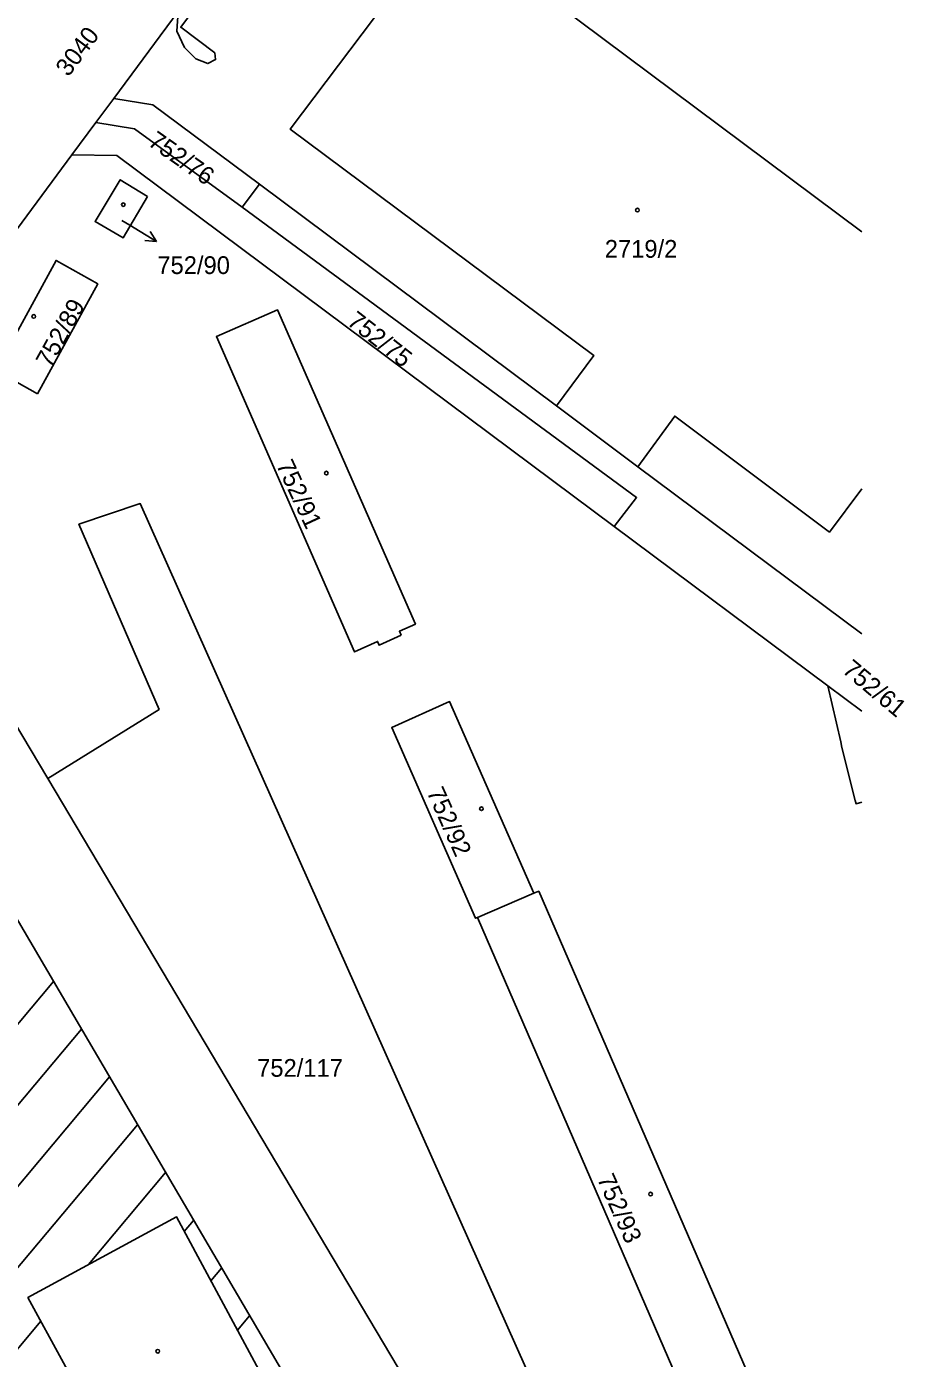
# Model space of a CAD drawing. Extents: x -496682 to -495776, y -1088797 to -1088018.
# Drawn here: x -496080.3 to -495996.2, y -1088434.2 to -1088306.6 of the extents above; entities that cross this region are included whole.
import ezdxf

# ---------------------------------------------------------------- set-up
doc = ezdxf.new("R2010")
doc.units = 0
for name, color, linetype in [('Hranice parcel', 7, 'Continuous'), ('Parcelní čísla', 7, 'Continuous'), ('Pop  PČ popisy', 7, 'Continuous'), ('Vrstva 20', 7, 'Continuous'), ('Značky budov', 7, 'Continuous')]:
    doc.layers.add(name, color=color, linetype=linetype)

msp = doc.modelspace()

# ---------------------------------------------------------------- linework, layer by layer
at = {"layer": 'Hranice parcel'}
for p, q in [((-496071.94, -1088313.44), (-496065.77, -1088305.12)), ((-496073.66, -1088315.77), (-496071.94, -1088313.44)), ((-496075.94, -1088318.85), (-496073.66, -1088315.77)), ((-496096.94, -1088347.2), (-496075.94, -1088318.85)), ((-496057.99, -1088321.67), (-496059.64, -1088323.87)), ((-496029.52, -1088342.93), (-496057.99, -1088321.67)), ((-496021.73, -1088348.76), (-496029.52, -1088342.93)), ((-496078.26, -1088378.65), (-496096.94, -1088347.2)), ((-496000.29, -1088364.76), (-496021.73, -1088348.76)), ((-496024.01, -1088354.47), (-496003.54, -1088369.74)), ((-496003.54, -1088369.74), (-496000.29, -1088372.17)), ((-496037.08, -1088391.95), (-496031.69, -1088389.64))]:
    msp.add_line(p, q, dxfattribs=at)
for points in [[(-496065.77, -1088305.12), (-496065.88, -1088306.99), (-496065.17, -1088308.57), (-496064.07, -1088309.66), (-496062.92, -1088310.11), (-496062.18, -1088309.72), (-496062.26, -1088309.09), (-496065.52, -1088306.62), (-496050.59, -1088286.56), (-496047.31, -1088288.98), (-496046.7, -1088288.89), (-496046.63, -1088288.12), (-496048.32, -1088286.61), (-496049.69, -1088286.17), (-496051.08, -1088286.43), (-496052.45, -1088287.51)], [(-496000.29, -1088326.22), (-496036.42, -1088299.21), (-496034.84, -1088297.11), (-496038.16, -1088294.64), (-496039.76, -1088296.76), (-496040.07, -1088296.53), (-496055.03, -1088316.4), (-496025.94, -1088338.1), (-496029.52, -1088342.93)], [(-496057.99, -1088321.67), (-496068.19, -1088314.06), (-496071.94, -1088313.44)], [(-496059.64, -1088323.87), (-496069.94, -1088316.36), (-496073.66, -1088315.77)], [(-496075.94, -1088318.85), (-496071.64, -1088318.92), (-496024.01, -1088354.47)], [(-496068.69, -1088322.84), (-496071.32, -1088321.24), (-496073.72, -1088325.26), (-496071.02, -1088326.81), (-496068.69, -1088322.84)], [(-496059.64, -1088323.87), (-496021.85, -1088351.71), (-496024.01, -1088354.47)], [(-496079.25, -1088341.76), (-496073.47, -1088331.22), (-496077.46, -1088328.98), (-496083.24, -1088339.52), (-496079.25, -1088341.76)], [(-496044.4, -1088364.9), (-496044.57, -1088364.53), (-496043.04, -1088363.83), (-496056.25, -1088333.7), (-496062.1, -1088336.28), (-496048.87, -1088366.5), (-496046.66, -1088365.5), (-496046.52, -1088365.86), (-496044.4, -1088364.9)], [(-496021.73, -1088348.76), (-496018.2, -1088343.9), (-496003.38, -1088355.01), (-496000.29, -1088350.87)], [(-496000.29, -1088504.86), (-496008.22, -1088489.48), (-496069.4, -1088352.28), (-496075.27, -1088354.26), (-496067.6, -1088372.01), (-496078.26, -1088378.65)], [(-496003.54, -1088369.74), (-496002.28, -1088375.11), (-496002.19, -1088375.66), (-496000.91, -1088380.74), (-496000.83, -1088381.05), (-496000.29, -1088380.91)], [(-496031.69, -1088389.64), (-496039.76, -1088371.27), (-496045.31, -1088373.74), (-496037.27, -1088392.03), (-496037.08, -1088391.95)], [(-496000.29, -1088509.9), (-496078.26, -1088378.65)], [(-496000.29, -1088530.17), (-496085.86, -1088384.22)], [(-496037.08, -1088391.95), (-496011.44, -1088451.19), (-496005.56, -1088448.7), (-496031.23, -1088389.44), (-496031.69, -1088389.64)], [(-496062.85, -1088443.39), (-496069.91, -1088447.16), (-496080.16, -1088428.4), (-496065.94, -1088420.65), (-496055.78, -1088439.53)]]:
    msp.add_lwpolyline(points, dxfattribs=at)
at = {"layer": 'Pop  PČ popisy'}
for p, q in [((-496071.17, -1088325.16), (-496070.41, -1088325.61)), ((-496070.41, -1088325.61), (-496067.84, -1088327.16)), ((-496067.84, -1088327.16), (-496068.44, -1088326.21)), ((-496067.84, -1088327.16), (-496068.95, -1088327.07))]:
    msp.add_line(p, q, dxfattribs=at)
at = {"layer": 'Vrstva 20'}
for p, q in [((-496155.67, -1088491), (-496077.71, -1088398.1)), ((-496151.92, -1088494.31), (-496075.03, -1088402.67)), ((-496148.18, -1088497.63), (-496072.34, -1088407.25)), ((-496144.43, -1088500.94), (-496069.66, -1088411.83)), ((-496074.37, -1088425.22), (-496066.97, -1088416.41)), ((-496065.18, -1088422.05), (-496064.29, -1088420.99)), ((-496062.63, -1088426.79), (-496061.6, -1088425.57)), ((-496140.69, -1088504.26), (-496078.92, -1088430.65)), ((-496060.08, -1088431.53), (-496058.92, -1088430.15))]:
    msp.add_line(p, q, dxfattribs=at)
at = {"layer": 'Značky budov'}
for centre in [(-496071.02, -1088323.63), (-496021.77, -1088324.15), (-496079.6, -1088334.34), (-496051.57, -1088349.36), (-496036.71, -1088381.53), (-496020.51, -1088418.48), (-496067.72, -1088433.54)]:
    msp.add_circle(centre, 0.175, dxfattribs=at)

# ---------------------------------------------------------------- texts
at = {"layer": 'Parcelní čísla'}
for s, rotation, p in [('3040', 53, (-496076.28, -1088311.45)), ('752/76', 325, (-496068.77, -1088317.86)), ('752/89', 61, (-496078.01, -1088339.37)), ('752/75', 322, (-496049.69, -1088335.05)), ('752/91', 295, (-496056.41, -1088348.57)), ('752/61', 320, (-496002.25, -1088368.4)), ('752/92', 294, (-496041.99, -1088379.93)), ('752/93', 294, (-496025.67, -1088417))]:
    msp.add_text(s, height=1.7, rotation=rotation, dxfattribs=at).set_placement(p)
for s, p in [('2719/2', (-496024.9, -1088328.72)), ('752/90', (-496067.76, -1088330.28)), ('752/117', (-496058.2, -1088407.23))]:
    msp.add_text(s, height=1.7, dxfattribs=at).set_placement(p)

doc.saveas('drawing.dxf')
